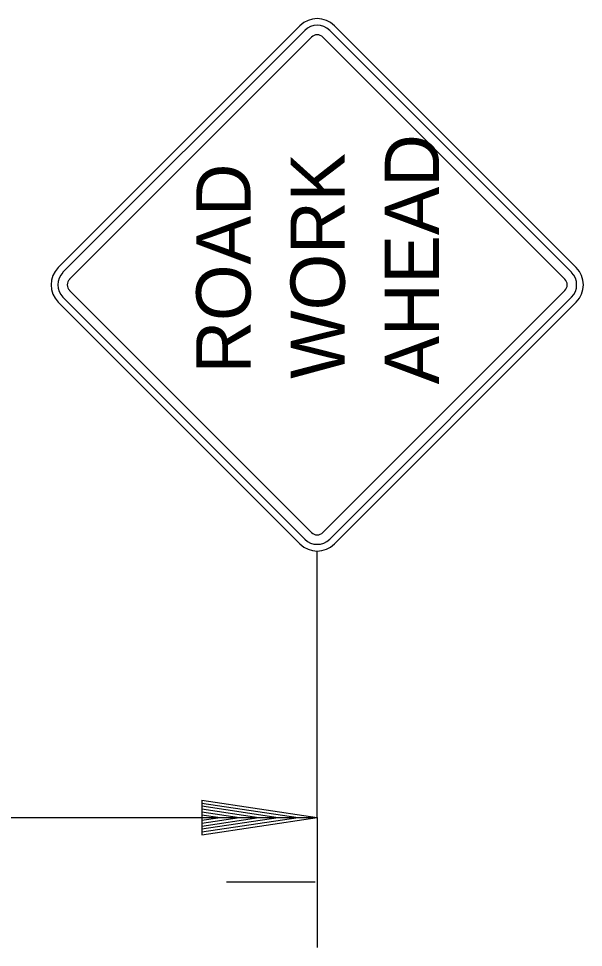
# Model space of a CAD drawing. Extents: x 913 to 1207, y 319 to 519.
# Drawn here: x 1104.8 to 1116.51, y 430.66 to 449.91 of the extents above; entities that cross this region are included whole.
import ezdxf

# ---------------------------------------------------------------- set-up
doc = ezdxf.new("R2010")
doc.units = 0
doc.layers.add('R_Annotation', color=7, linetype='Continuous')
doc.layers.add('R_Draft', color=7, linetype='Continuous')

msp = doc.modelspace()

# ---------------------------------------------------------------- linework, layer by layer
at = {"layer": 'R_Annotation'}
for p, q in [((1105.619, 444.747), (1110.63, 449.759)), ((1111.346, 449.759), (1116.358, 444.747)), ((1105.718, 444.648), (1110.73, 449.659)), ((1105.857, 444.508), (1110.869, 449.52)), ((1111.108, 449.52), (1116.119, 444.508)), ((1111.247, 449.659), (1116.258, 444.648)), ((1110.73, 439.119), (1105.718, 444.131)), ((1110.869, 439.258), (1105.857, 444.27)), ((1116.119, 444.27), (1111.108, 439.258)), ((1116.258, 444.131), (1111.247, 439.119)), ((1110.63, 439.019), (1105.619, 444.031)), ((1116.358, 444.031), (1111.346, 439.019))]:
    msp.add_line(p, q, dxfattribs=at)
for centre, radius, start, end in [((1110.988, 449.401), 0.506, 45, 135), ((1110.988, 449.401), 0.366, 45, 135), ((1110.988, 449.401), 0.169, 45, 135), ((1105.977, 444.389), 0.506, 135, 225), ((1116, 444.389), 0.506, 315, 45), ((1105.977, 444.389), 0.366, 135, 225), ((1105.977, 444.389), 0.169, 135, 225), ((1116, 444.389), 0.169, 315, 45), ((1116, 444.389), 0.366, 315, 45), ((1110.988, 439.377), 0.366, 225, 315), ((1110.988, 439.377), 0.169, 225, 315), ((1110.988, 439.377), 0.506, 225, 315)]:
    msp.add_arc(centre, radius, start, end, dxfattribs=at)
at = {"layer": 'R_Draft'}
for p, q in [((1110.988, 433.35), (1110.988, 438.871)), ((1108.596, 433.709), (1110.99, 433.35)), ((1108.596, 433.709), (1108.596, 432.991)), ((1108.596, 433.649), (1110.59, 433.35)), ((1108.596, 433.589), (1110.178, 433.35)), ((1108.596, 433.529), (1109.78, 433.35)), ((1075.269, 433.35), (1110.99, 433.35)), ((1108.596, 433.466), (1109.374, 433.35)), ((1108.596, 433.406), (1108.974, 433.35)), ((1108.596, 432.991), (1110.99, 433.35)), ((1108.596, 433.233), (1109.374, 433.35)), ((1108.596, 433.112), (1110.178, 433.35)), ((1108.596, 433.051), (1110.59, 433.35)), ((1108.596, 433.171), (1109.78, 433.35)), ((1108.596, 433.294), (1108.974, 433.35)), ((1110.988, 433.35), (1110.988, 430.657)), ((1110.949, 432.01), (1109.111, 432.01))]:
    msp.add_line(p, q, dxfattribs=at)

# ---------------------------------------------------------------- texts
at = {"layer": 'R_Annotation'}
for s, p in [(' AHEAD ', (1113.513, 441.908)), ('WORK', (1111.56, 442.441)), (' ROAD ', (1109.606, 442.136))]:
    msp.add_text(s, height=1.125, rotation=90, dxfattribs=at).set_placement(p)

doc.saveas('drawing.dxf')
